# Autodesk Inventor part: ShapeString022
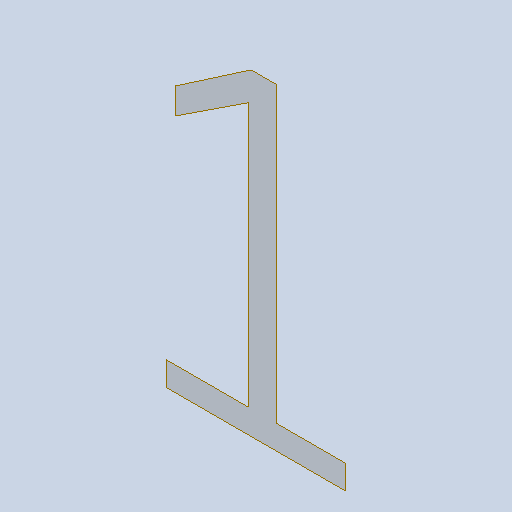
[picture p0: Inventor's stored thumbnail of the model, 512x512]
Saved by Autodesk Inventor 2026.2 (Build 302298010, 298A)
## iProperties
Created: 2026-10
Part Number: ShapeString022
Material: Générique
Document SubType Name: Modeling
Designer: mel
Density: 1 g/cm^3
Appearance: Par défaut
Author: mel
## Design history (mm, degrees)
feature "Composite1"
body "Srf1"
